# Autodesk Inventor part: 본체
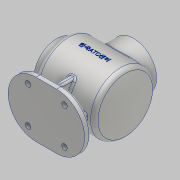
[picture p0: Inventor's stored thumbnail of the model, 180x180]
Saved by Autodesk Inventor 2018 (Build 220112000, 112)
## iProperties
Created: 2023-01
Part Number: 본체
Material: 알루미늄 6061
Document SubType Name: Modeling
Designer: home
Density: 2.7 g/cm^3
Appearance: 알루미늄 - 평지
Mass: 1034.39 g
Surface Area: 1157.53 cm^2
Volume: 383.109 cm^3
Author: home
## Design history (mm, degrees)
sketch "스케치1"
  geometry: L1 (51, -50)-(-48.087, -50); L2 (63, 0)-(63, -38); L3 (63, -38)-(51, -38); L4 (51, -38)-(51, -50); L5 (63, -27)-(46, -27); L6 (46, -27)-(46, -45); L7 (46, -45)-(-44.83, -45); L8 (63, 0)-(-59, 0); L9 (0, -78.298)-(0, 115.666) reference; A1 r 120 centre (61, 0) between (-59, 0) and (-48.087, -50); A2 r 115 centre (61, 0) between (-54, 0) and (-44.83, -45)
  constraints: 16 end point, 4 horizontal, 4 point on circle, 3 perpendicular, 2 centre point, 2 point on line, 1 parallel
  dimensions: "d8" = 122 distance from line of L8.end L2; "d9" = 100 diameter of L1 L8; "d10" = 76 diameter of L3 L8; "d11" = 5 radial gap between concentric circles of A1 A2; "d12" = 90 diameter of L7 L8; "d13" = 54 diameter of L5 L8; "d17" = 2 distance from line of A1.centre L2; "d18" = 12 distance between parallel lines of L4 L2; "d19" = 17 distance between parallel lines of L6 L2; "d20" = 120 radius of A1; "d51" = 59 distance from line of L8.end L9; "d52" = 153.66597 distance from line of L9.end L3
revolve "회전1" sketch "스케치1" stored, may be unused: angle "d21" = 90 deg
node "작업 평면1"
sketch "스케치2"
  geometry: L1 (63, 38)-(63, -38) reference; L2 (17, -46)-(-17, -46); L3 (17, 46)-(-17, 46); A1 r 46 centre (-17, 0) between (-17, 46) and (-17, -46); A2 r 46 centre (17, 0) between (17, -46) and (17, 46); 2 further points
  constraints: 4 end point, 4 point on circle, 4 tangent, 2 centre point, 2 horizontal, 1 horizontal alignment, 1 midpoint
  dimensions: "d26" = 46 radius of A2; "d27" = 8 distance from line of L1.start L3; "d28" = 80 distance from line of L3.end L1
extrude "돌출1" join sketch "스케치2" distance "d29" = 10; taper "d30" = 0 deg
sketch "스케치4"
  geometry: L1 (-17, 46)-(17, 46) reference; L2 (17, -46)-(-17, -46) reference; A1 r 46 centre (17, 0) between (17, -46) and (17, 46) reference; A2 r 46 centre (-17, 0) between (-17, 46) and (-17, -46) reference; 5 further points
  constraints: 2 horizontal alignment, 2 vertical alignment
  dimensions: "d35" = 60 distance of point (-30, -30) point (30, -30); "d36" = 30 horizontal distance of point (0, 0) point (30, -30); "d37" = 60 distance of point (30, 30) point (30, -30); "d38" = 30 horizontal distance of point (0, 0) point (30, 30)
hole "구멍1" sketch "스케치4" at (30, -30), (-30, -30), (30, 30), (-30, 30) diameter "d39" = 9; stored, may be unused: countersink angle "d43" = 90 deg, drill point angle "d45" = 118 deg; dims "d40" = 6, "d41" = 4, "d42" = 2, "d44" = 8
sketch "스케치5"
  geometry: L1 (5, -35)-(-5, -35); L2 (-5, -35)-(-5, 35); L3 (-5, 35)-(5, 35); L4 (5, 35)-(5, -35); L5 (-63, 0)-(-63, -87.957); L6 (63, 0)-(63, -82.259); A1 r 46 centre (17, 0) between (17, -46) and (17, 46) reference; A2 r 46 centre (-17, 0) between (-17, 46) and (-17, -46) reference; 2 further points
  constraints: 12 end point, 2 parallel, 2 point on circle, 2 vertical, 1 horizontal, 1 horizontal alignment, 1 midpoint, 1 perpendicular, 1 tangent
  dimensions: "d46" = 10 distance of L2.end L3.end; "d47" = 70 distance of L1.end L2.end; "d53" = 58 distance between parallel lines of L2 L5
extrude "돌출3" join sketch "스케치5" stored distance "d54" = 10; taper "d55" = 0 deg
sketch "스케치6"
  geometry: L1 (-51, -50)-(48.087, -50) reference; L2 (-17, -70)-(17, -70) reference; L3 (-17, -80)-(-17, -80) reference; L4 (-17, -80)-(-17, -70) reference; L5 (-17, -70)-(-17, -70) reference; L6 (-17, -80)-(-17, -70) reference; L7 (-34.5, -70)-(-25.5, -70) reference; L8 (-17, -70)-(-63, -70) reference; L9 (-34.641, -50)-(-40, -70); 1 further point
  constraints: 2 end point, 1 midpoint, 1 point on line
  dimensions: "d56" = 105 deg angle of L8 L9; "d57" = 23 distance of L8.end L9.end
feature "리브1" sketch "스케치6" dims "d58" = 1, "d59" = 10, "d60" = 0, "d61" = 0, "d62" = 1, "d63" = 1
node "작업 평면2"
sketch "스케치8"
  geometry: C1 r 38 at (0, 0); 1 further point
  constraints: 1 centre point, 1 coincident
  dimensions: "d65" = 76 diameter of C1
extrude "돌출4" join sketch "스케치8" stored distance "d66" = 10; taper "d67" = 0 deg
hole "구멍2" diameter "d70" = 54; stored, may be unused: countersink angle "d74" = 90 deg, drill point angle "d76" = 118 deg; dims "d68" = 10, "d69" = 10, "d71" = 6, "d72" = 4, "d73" = 2, "d75" = 8
sketch "스케치9"
  geometry: 5 further points
  constraints: 5 other
  dimensions: "d80" = 360 deg dimension on point (0, 0) point (0, -32.5) (derived)
hole "구멍3" sketch "스케치9" at (0, -32.5), (32.5, 0), (0, 32.5), (-32.5, 0) diameter "d82" = 3.242; stored, may be unused: countersink angle "d86" = 90 deg, drill point angle "d88" = 118 deg; dims "d83" = 8, "d84" = 4, "d85" = 2, "d87" = 10
sketch "스케치10"
  geometry: 5 further points
  constraints: 5 other
  dimensions: "d92" = 360 deg dimension on point (0, 0) point (0, 32.5) (derived)
hole "구멍4" sketch "스케치10" at (0, 32.5), (-32.5, 0), (0, -32.5), (32.5, 0) diameter "d94" = 3.242; stored, may be unused: countersink angle "d98" = 90 deg, drill point angle "d100" = 118 deg; dims "d95" = 8, "d96" = 4, "d97" = 2, "d99" = 10
fillet "모깎기1" dims "d101" = 3
fillet "모깎기2" dims "d102" = 3
fillet "모깎기3" dims "d103" = 8
fillet "모깎기4" dims "d104" = 3
fillet "모깎기5" dims "d105" = 8
chamfer "모따기1" distance "d106" = 1; stored, may be unused: second distance "d107" = 2, angle "d108" = 45 deg
fillet "모깎기6" dims "d109" = 3
node "작업 평면3"
sketch "스케치11"
  geometry: L1 (-61.544, -38)-(-61.544, 38) reference; L2 (18.456, -80)-(-15.544, -80) reference; 2 further points
  constraints: 1 other
  dimensions: "d110" = 63 distance from line of point (1.456, 0) L1; "d111" = 80 distance from line of point (1.456, 0) L2
feature "엠보싱1" sketch "스케치11" dims "d26" = 46, "d112" = 0.5, "d113" = 0
node "솔리드1"
mirror "미러1"
node "투영된 루프1"
node "투영된 루프2"
other parameters: "d3" = 122, "d23" = 92, "d24" = 92, "d64" = -144
